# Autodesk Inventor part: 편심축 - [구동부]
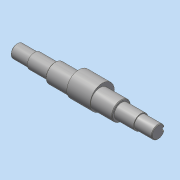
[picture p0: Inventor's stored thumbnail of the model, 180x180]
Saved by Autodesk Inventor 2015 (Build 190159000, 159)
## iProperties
Created: 2015-10
Part Number: 편심축 - [구동부]
Document SubType Name: Modeling
Designer: mdu
Density: 7.86 g/cm^3
Material: 강철, 연강
Mass: 1327.93 g
Surface Area: 248.524 cm^2
Volume: 168.947 cm^3
Appearance: 강철
Author: mdu
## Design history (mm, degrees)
sketch "스케치1"
  geometry: L1 (-20.5, -41.331)-(-20.5, 32.669) reference; L2 (7.5, -30.031)-(7.5, 21.369) reference; L3 (135.5, -30.331)-(135.5, 21.669) reference; L4 (121.5, 21.369)-(121.5, -30.031) reference; L5 (184.5, -4.331)-(-57.5, -4.331); L6 (184.5, -4.331)-(184.5, 6.669); L7 (154.5, 8.169)-(121.5, 8.169); L8 (121.5, 8.169)-(121.5, 11.669); L9 (121.5, 11.669)-(7.5, 11.669); L10 (7.5, 11.669)-(7.5, 8.169); L11 (7.5, 8.169)-(-27.5, 8.169); L12 (-27.5, 8.169)-(-27.5, 6.669); L13 (-27.5, 6.669)-(-57.5, 6.669); L14 (-57.5, 6.669)-(-57.5, -4.331); L15 (154.5, 8.169)-(154.5, 6.669); L16 (154.5, 6.669)-(184.5, 6.669); C1 r 32.5 at (64.5, -4.331) reference; 1 further point
  constraints: 24 end point, 8 perpendicular, 5 point on line, 3 parallel, 2 collinear
  dimensions: "d1" = 25 diameter of L11 L5; "d2" = 32 diameter of L9 L5; "d3" = 22 diameter of L13 L5; "d4" = 35 distance of L10.end L11.end; "d5" = 30 distance of L12.end L13.end; "d15" = 33 distance of L7.start L7.end; "d26" = 30 distance of L15.end L6.end
revolve "회전1" sketch "스케치1" stored, may be unused: angle "d6" = 90 deg
node "작업 평면1"
sketch "스케치2"
  geometry: C1 r 16 at (0, 0) reference; C2 r 16 at (0, 0) reference; C3 r 20.75 at (0, 4); C4 r 16 at (0, 0) reference; 1 further point
  constraints: 1 centre point, 1 vertical alignment
  dimensions: "d8" = 41.5 diameter of C3; "d25" = 4 distance of C3.centre C1.centre
extrude "돌출1" join sketch "스케치2" stored distance "d9" = 40; taper "d10" = 0 deg
chamfer "모따기1" distance "d11" = 1; stored, may be unused: second distance "d12" = 2, angle "d13" = 45 deg
node "작업 평면2"
sketch "스케치3"
  geometry: L1 (-15, -10)-(-15, 10) reference; L2 (-15, 3)-(0, 3); L3 (0, -3)-(-15, -3); A1 r 3 centre (0, 0) between (0, -3) and (0, 3); 2 further points
  constraints: 4 end point, 2 perpendicular, 2 point on circle, 2 point on line, 2 tangent, 1 centre point, 1 horizontal alignment, 1 midpoint
  dimensions: "d16" = 18 dimension on A1 L1; "d17" = 6 distance between parallel lines of L3 L2
extrude "돌출2" cut sketch "스케치3" distance "d18" = 3.5; taper "d19" = 0 deg
node "작업 평면3"
node "솔리드1"
mirror "대칭1"
node "참조1"
node "참조2"
node "참조3"
node "참조4"
node "참조5"
node "투영된 루프1"
